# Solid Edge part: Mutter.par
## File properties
Sűrűség: 0,000 kg/m^3
Pontosság: 0,990
Author: ahadarics
Last saved by: psaghy
Revision: 77
Username: ahadarics
Dokumentum tartalom típus: 0
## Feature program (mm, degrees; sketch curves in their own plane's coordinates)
base feature "unnamed BaseFeature 1"
sketch for "Furat_1" plane through (7, 0, 0) normal (1, 0, 0) x-axis (0, -1, 0)
hole "Furat_1" through  StartChamferOffset = 0.39 mm; StartChamferAngle = 45 deg
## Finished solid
Body 1: solid body, 23 faces, 47 edges, 26 vertices.
  Faces by surface: cone 14, plane 8, cylinder 1
  Edges by curve: spline 24, circle 16, line 7
Bounding box of the edges (mm): 7.000 x 21.939 x 19.000, from (0, -10.9697, -9.5) to (7, 10.9697, 9.5).
Cylindrical faces by radius (mm): R5.3235 x1
Conical faces (half-angle, radius in mm at the cone's reference point): 45 deg R5.7135 x1, 60 deg R5.6618 x1, 60 deg R10.2348 x12
Planar faces by outward normal: +x 1, +z 1, -x 1, -z 1, oblique 4
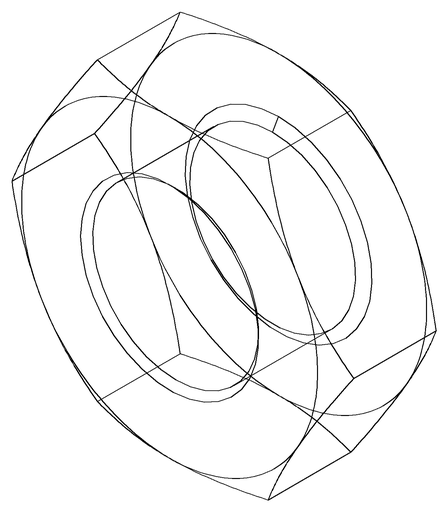
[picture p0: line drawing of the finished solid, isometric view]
